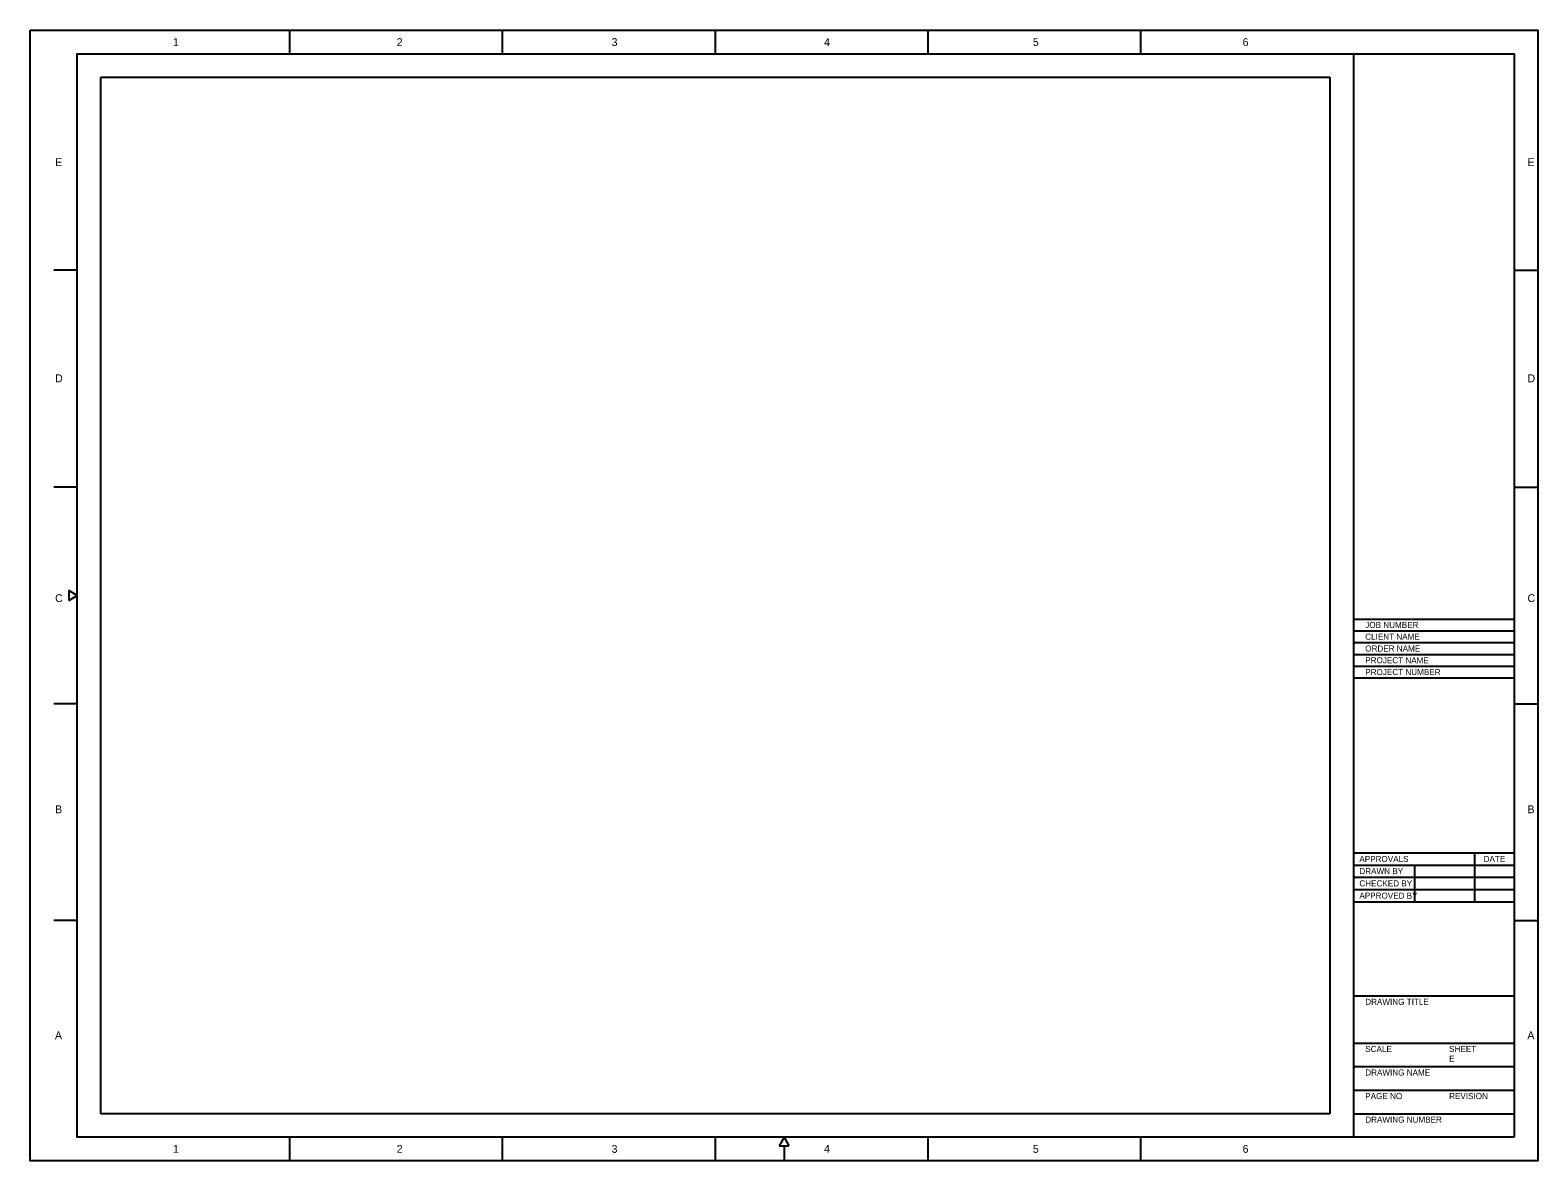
# Model space of a CAD drawing. Extents: x 0 to 4, y 0 to 3.
import ezdxf

# ---------------------------------------------------------------- set-up
doc = ezdxf.new("R2010")
doc.units = 0
for name, color, linetype in [('Border', 7, 'Continuous'), ('BorderPlot', 7, 'Continuous'), ('ClipShape', 7, 'Continuous'), ('STSF-BORDER', 7, 'Continuous'), ('TitleBlock', 7, 'Continuous')]:
    doc.layers.add(name, color=color, linetype=linetype)

# ---------------------------------------------------------------- blocks, each defined once
blk = doc.blocks.new('DC-ARCH-E')
at = {"layer": 'Border'}
for p, q in [((0.6893, 2.9375), (0.6893, 3)), ((1.2536, 2.9375), (1.2536, 3)), ((1.8179, 2.9375), (1.8179, 3)), ((2.3822, 2.9375), (2.3822, 3)), ((2.9465, 2.9375), (2.9465, 3)), ((3.5108, 2.9375), (3.5108, 0.0625)), ((0.125, 2.3628), (0.0625, 2.3628)), ((3.9375, 2.3628), (4, 2.3628)), ((0.125, 1.7875), (0.0625, 1.7875)), ((3.9375, 1.7875), (4, 1.7875)), ((0.125, 1.5), (0.1024, 1.513)), ((0.1024, 1.513), (0.1024, 1.487)), ((0.1024, 1.487), (0.125, 1.5)), ((0.125, 1.2125), (0.0625, 1.2125)), ((3.9375, 1.2125), (4, 1.2125)), ((0.125, 0.6375), (0.0625, 0.6375)), ((3.9375, 0.6375), (4, 0.6375)), ((0.6893, 0), (0.6893, 0.0625)), ((1.2536, 0), (1.2536, 0.0625)), ((1.8179, 0), (1.8179, 0.0625)), ((2, 0.0625), (1.987, 0.0399)), ((2, 0.0625), (2.013, 0.0399)), ((2.3822, 0), (2.3822, 0.0625)), ((2.9465, 0), (2.9465, 0.0625)), ((1.987, 0.0399), (2.013, 0.0399)), ((2, 0.0399), (2, 0))]:
    blk.add_line(p, q, dxfattribs=at)
blk.add_lwpolyline([(3.9375, 0.0625), (0.125, 0.0625), (0.125, 2.9375), (3.9375, 2.9375)], close=True, dxfattribs=at)
at = {"layer": 'BorderPlot'}
blk.add_lwpolyline([(0, 3), (4, 3), (4, 0), (0, 0)], close=True, dxfattribs=at)
at = {"layer": 'ClipShape'}
for p, q in [((0.1875, 0.125), (0.1875, 2.875)), ((0.1875, 2.875), (3.4483, 2.875)), ((3.4483, 2.875), (3.4483, 0.125)), ((3.4483, 0.125), (0.1875, 0.125))]:
    blk.add_line(p, q, dxfattribs=at)
at = {"layer": 'TitleBlock'}
for p, q in [((3.5108, 1.4375), (3.9375, 1.4375)), ((3.5108, 1.4062), (3.9375, 1.4062)), ((3.5108, 1.375), (3.9375, 1.375)), ((3.5108, 1.375), (3.9375, 1.375)), ((3.5108, 1.3437), (3.9375, 1.3437)), ((3.5108, 1.3125), (3.9375, 1.3125)), ((3.5108, 1.3125), (3.9375, 1.3125)), ((3.5108, 1.2812), (3.9375, 1.2812)), ((3.5108, 0.8174), (3.9375, 0.8174)), ((3.8332, 0.6875), (3.8332, 0.8174)), ((3.5108, 0.7849), (3.9375, 0.7849)), ((3.6736, 0.6875), (3.6736, 0.7849)), ((3.5108, 0.7525), (3.9375, 0.7525)), ((3.5108, 0.72), (3.9375, 0.72)), ((3.5108, 0.6875), (3.9375, 0.6875)), ((3.5108, 0.4375), (3.9375, 0.4375)), ((3.5108, 0.3125), (3.9375, 0.3125)), ((3.5108, 0.3125), (3.9375, 0.3125)), ((3.5108, 0.25), (3.9375, 0.25)), ((3.5108, 0.25), (3.9375, 0.25)), ((3.5108, 0.1875), (3.9375, 0.1875)), ((3.5108, 0.1875), (3.9375, 0.1875)), ((3.5108, 0.125), (3.9375, 0.125)), ((3.9375, 0.0625), (3.9375, 0.0625)), ((3.9375, 0.0625), (3.9375, 0.0625))]:
    blk.add_line(p, q, dxfattribs=at)
at = {"layer": 'Border'}
for s, p in [('1', (0.3789, 2.9579)), ('2', (0.9725, 2.9579)), ('3', (1.5427, 2.9579)), ('4', (2.1063, 2.9579)), ('5', (2.6602, 2.9579)), ('6', (3.2168, 2.9579)), ('E', (0.0664, 2.6392)), ('E', (3.9727, 2.6392)), ('D', (0.0663, 2.0658)), ('D', (3.9726, 2.0658)), ('C', (0.0663, 1.4826)), ('C', (3.9726, 1.4826)), ('B', (0.0663, 0.9223)), ('B', (3.9726, 0.9223)), ('A', (0.0659, 0.3228)), ('A', (3.9722, 0.3228)), ('1', (0.3789, 0.0213)), ('2', (0.9725, 0.0213)), ('3', (1.5427, 0.0213)), ('4', (2.1063, 0.0213)), ('5', (2.6602, 0.0213)), ('6', (3.2168, 0.0213))]:
    blk.add_text(s, height=0.0208, dxfattribs=at).set_placement(p)
at = {"layer": 'STSF-BORDER'}
for s, height, p in [('JOB NUMBER', 0.0161, (3.5421, 1.4138)), ('ORDER NAME', 0.0161, (3.5421, 1.3513)), ('CLIENT NAME', 0.016098, (3.5421, 1.3826)), ('PROJECT NAME', 0.016098, (3.5421, 1.3201)), ('PROJECT NUMBER', 0.016098, (3.5421, 1.2888)), ('APPROVALS', 0.0161, (3.5265, 0.7929)), ('DATE', 0.0161, (3.8561, 0.7931)), ('DRAWN BY', 0.0161, (3.5265, 0.7607)), ('CHECKED BY', 0.0161, (3.5265, 0.7282)), ('APPROVED BY', 0.016098, (3.5265, 0.6957)), ('DRAWING TITLE', 0.016098, (3.5421, 0.4138)), ('SCALE', 0.0161, (3.5421, 0.2888)), ('SHEET', 0.0161, (3.7646, 0.2888)), ('DRAWING NAME', 0.016098, (3.5421, 0.2263)), ('E', 0.0161, (3.7646, 0.2631)), ('PAGE NO', 0.0161, (3.5421, 0.1638)), ('REVISION', 0.0161, (3.7646, 0.1638)), ('DRAWING NUMBER', 0.016098, (3.5421, 0.1013))]:
    blk.add_text(s, height=height, dxfattribs=at).set_placement(p)

msp = doc.modelspace()

# ---------------------------------------------------------------- block references
msp.add_blockref('DC-ARCH-E', (0, 0))

doc.saveas('drawing.dxf')
